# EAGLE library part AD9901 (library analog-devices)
Ultrahigh Speed Phase/Frequency Discrimainator Phase-Locked-Loop Source: 36342005AD9901_b.pdf
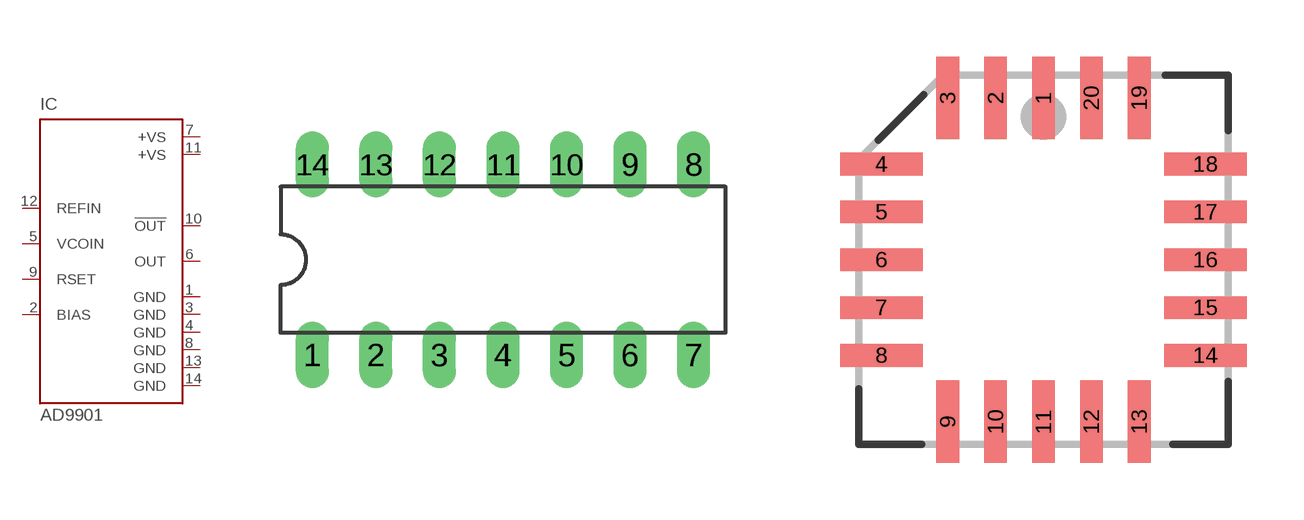
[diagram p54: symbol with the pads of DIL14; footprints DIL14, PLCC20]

Designator prefix IC

## AD9901P (MF: ALTERA CORPORATION; MPN: AD9901KQ; OC_FARNELL: unknown; OC_NEWARK: 05F7832)  [DIL14]
1  GND  in
2  BIAS  in
3  GND  in
4  GND  in
5  VCOIN  in
6  OUT  in
7  +VS  in
8  GND  in
9  RSET  in
10  !OUT  in
11  +VS  in
12  REFIN  out
13  GND  in
14  GND  in

## AD9901PL (MF: ALTERA CORPORATION; MPN: AD9901KP; OC_FARNELL: 1424271; OC_NEWARK: 83F3495)  [PLCC20]
2  GND  in
3  BIAS  in
4  GND  in
5  GND  in
6  VCOIN  in
7  OUT  in
10  +VS  in
12  GND  in
13  RSET  in
14  !OUT  in
16  +VS  in
18  REFIN  out
19  GND  in
20  GND  in

## AD9901LC (MF: ALTERA CORPORATION; MPN: AD9901KPZ; OC_FARNELL: 1676470; OC_NEWARK: 59K7524)  [LCC20]
2  GND  in
3  BIAS  in
4  GND  in
6  GND  in
8  VCOIN  in
9  OUT  in
10  +VS  in
12  GND  in
13  RSET  in
14  !OUT  in
16  +VS  in
18  REFIN  out
19  GND  in
20  GND  in

## Footprint DIL14 (pad centres in mm)
Dual In Line Package
drill 0.813 long: 1 -7.62,-3.81; 2 -5.08,-3.81; 3 -2.54,-3.81; 4 0,-3.81; 5 2.54,-3.81; 6 5.08,-3.81; 7 7.62,-3.81; 8 7.62,3.81; 9 5.08,3.81; 10 2.54,3.81; 11 0,3.81; 12 -2.54,3.81; 13 -5.08,3.81; 14 -7.62,3.81

## Footprint PLCC20 (pad centres in mm)
Plastic Leaded Chip Carrier IPC standard
smd 0.6 x 2.2: 1 0,4.3; 2 -1.27,4.3; 3 -2.54,4.3; 9 -2.54,-4.3; 10 -1.27,-4.3; 11 0,-4.3; 12 1.27,-4.3; 13 2.54,-4.3; 19 2.54,4.3; 20 1.27,4.3
smd 2.2 x 0.6: 4 -4.3,2.54; 5 -4.3,1.27; 6 -4.3,0; 7 -4.3,-1.27; 8 -4.3,-2.54; 14 4.3,-2.54; 15 4.3,-1.27; 16 4.3,0; 17 4.3,1.27; 18 4.3,2.54

## Footprint LCC20 (pad centres in mm)
PLASTIC LEADED CHIP CARRIER
smd 0.8 x 3.4: 1 0,3.8
smd 0.8 x 2: 2 -1.27,4.5; 3 -2.54,4.5; 9 -2.54,-4.5; 10 -1.27,-4.5; 11 0,-4.5; 12 1.27,-4.5; 13 2.54,-4.5; 19 2.54,4.5; 20 1.27,4.5
smd 2 x 0.8: 4 -4.5,2.54; 5 -4.5,1.27; 6 -4.5,0; 7 -4.5,-1.27; 8 -4.5,-2.54; 14 4.5,-2.54; 15 4.5,-1.27; 16 4.5,0; 17 4.5,1.27; 18 4.5,2.54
